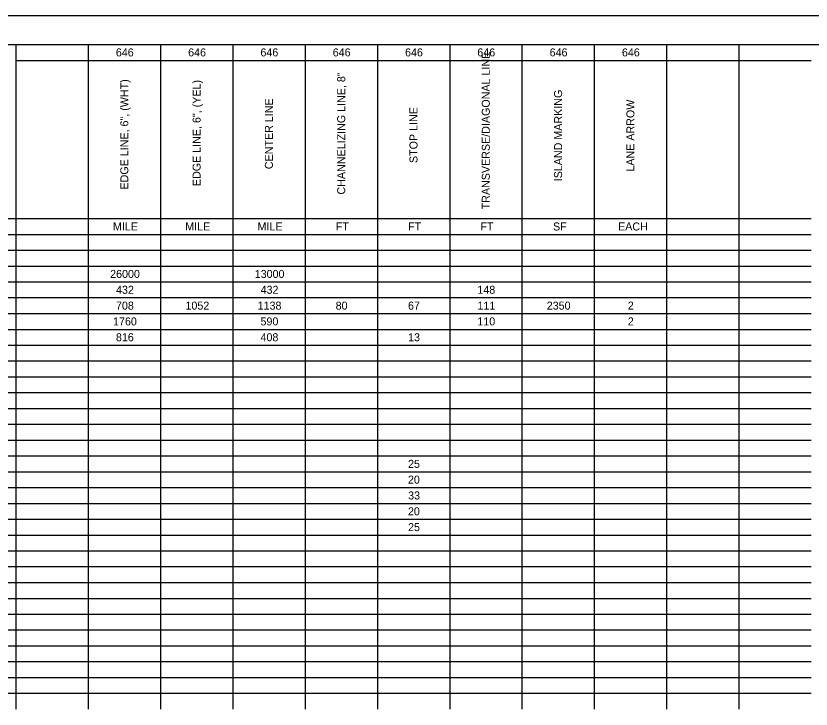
# Model space of a CAD drawing. Extents: x 0 to 34, y 0 to 22.
# Drawn here: x 13.03 to 26.94, y 9.88 to 22 of the extents above; entities that cross this region are included whole.
import ezdxf

# ---------------------------------------------------------------- set-up
doc = ezdxf.new("R2010")
doc.units = 0
for name, color, linetype in [('SH_Border', 7, 'Continuous'), ('SH_Cut_Line', 7, 'Continuous'), ('SH_Text', 7, 'Continuous')]:
    doc.layers.add(name, color=color, linetype=linetype)

msp = doc.modelspace()

# ---------------------------------------------------------------- linework, layer by layer
at = {"layer": 'SH_Border'}
msp.add_lwpolyline([(1.5, 21.5), (33.5, 21.5), (33.5, 0.5), (1.5, 0.5)], close=True, dxfattribs=at)
at = {"layer": 'SH_Cut_Line'}
msp.add_lwpolyline([(0, 0), (34, 0), (34, 22), (0, 22)], close=True, dxfattribs=at)
at = {"layer": 'SH_Text'}
for p, q in [((8.427, 21.5), (13.026, 21.5)), ((13.026, 21.5), (15.556, 21.5)), ((13.026, 21.5), (13.026, 21.223)), ((14.291, 21.5), (14.291, 21.223)), ((15.556, 21.5), (23.145, 21.5)), ((15.556, 21.5), (15.556, 21.223)), ((16.821, 21.5), (16.821, 21.223)), ((18.086, 21.5), (18.086, 21.223)), ((19.351, 21.5), (19.351, 21.223)), ((20.616, 21.5), (20.616, 21.223)), ((21.88, 21.5), (21.88, 21.223)), ((23.145, 21.5), (24.41, 21.5)), ((23.145, 21.5), (23.145, 21.223)), ((24.41, 21.5), (25.675, 21.5)), ((24.41, 21.5), (24.41, 21.223)), ((25.675, 21.5), (26.94, 21.5)), ((25.675, 21.5), (25.675, 21.223)), ((13.026, 21.223), (15.556, 21.223)), ((13.026, 21.223), (13.026, 20.947)), ((14.291, 21.223), (14.291, 20.947)), ((15.556, 21.223), (23.145, 21.223)), ((15.556, 21.223), (15.556, 20.947)), ((16.821, 21.223), (16.821, 20.947)), ((18.086, 21.223), (18.086, 20.947)), ((19.351, 21.223), (19.351, 20.947)), ((20.616, 21.223), (20.616, 20.947)), ((21.88, 21.223), (21.88, 20.947)), ((23.145, 21.223), (24.41, 21.223)), ((23.145, 21.223), (23.145, 20.947)), ((24.41, 21.223), (25.675, 21.223)), ((24.41, 21.223), (24.41, 20.947)), ((25.675, 21.223), (26.94, 21.223)), ((25.675, 21.223), (25.675, 20.947)), ((13.026, 20.947), (13.026, 20.67)), ((14.291, 20.947), (14.291, 20.67)), ((15.556, 20.947), (15.556, 20.67)), ((16.821, 20.947), (16.821, 20.67)), ((18.086, 20.947), (18.086, 20.67)), ((19.351, 20.947), (19.351, 20.67)), ((20.616, 20.947), (20.616, 20.67)), ((21.88, 20.947), (21.88, 20.67)), ((23.145, 20.947), (23.145, 20.67)), ((24.41, 20.947), (24.41, 20.67)), ((25.675, 20.947), (25.675, 20.67)), ((13.026, 20.67), (13.026, 20.393)), ((14.291, 20.67), (14.291, 20.393)), ((15.556, 20.67), (15.556, 20.393)), ((16.821, 20.67), (16.821, 20.393)), ((18.086, 20.67), (18.086, 20.393)), ((19.351, 20.67), (19.351, 20.393)), ((20.616, 20.67), (20.616, 20.393)), ((21.88, 20.67), (21.88, 20.393)), ((23.145, 20.67), (23.145, 20.393)), ((24.41, 20.67), (24.41, 20.393)), ((25.675, 20.67), (25.675, 20.393)), ((13.026, 20.393), (13.026, 20.116)), ((14.291, 20.393), (14.291, 20.116)), ((15.556, 20.393), (15.556, 20.116)), ((16.821, 20.393), (16.821, 20.116)), ((18.086, 20.393), (18.086, 20.116)), ((19.351, 20.393), (19.351, 20.116)), ((20.616, 20.393), (20.616, 20.116)), ((21.88, 20.393), (21.88, 20.116)), ((23.145, 20.393), (23.145, 20.116)), ((24.41, 20.393), (24.41, 20.116)), ((25.675, 20.393), (25.675, 20.116)), ((13.026, 20.116), (13.026, 19.84)), ((14.291, 20.116), (14.291, 19.84)), ((15.556, 20.116), (15.556, 19.84)), ((16.821, 20.116), (16.821, 19.84)), ((18.086, 20.116), (18.086, 19.84)), ((19.351, 20.116), (19.351, 19.84)), ((20.616, 20.116), (20.616, 19.84)), ((21.88, 20.116), (21.88, 19.84)), ((23.145, 20.116), (23.145, 19.84)), ((24.41, 20.116), (24.41, 19.84)), ((25.675, 20.116), (25.675, 19.84)), ((13.026, 19.84), (13.026, 19.563)), ((14.291, 19.84), (14.291, 19.563)), ((15.556, 19.84), (15.556, 19.563)), ((16.821, 19.84), (16.821, 19.563)), ((18.086, 19.84), (18.086, 19.563)), ((19.351, 19.84), (19.351, 19.563)), ((20.616, 19.84), (20.616, 19.563)), ((21.88, 19.84), (21.88, 19.563)), ((23.145, 19.84), (23.145, 19.563)), ((24.41, 19.84), (24.41, 19.563)), ((25.675, 19.84), (25.675, 19.563)), ((13.026, 19.563), (13.026, 19.01)), ((14.291, 19.563), (14.291, 19.01)), ((15.556, 19.563), (15.556, 19.01)), ((16.821, 19.563), (16.821, 19.01)), ((18.086, 19.563), (18.086, 19.01)), ((19.351, 19.563), (19.351, 19.01)), ((20.616, 19.563), (20.616, 19.01)), ((21.88, 19.563), (21.88, 19.01)), ((23.145, 19.563), (23.145, 19.01)), ((24.41, 19.563), (24.41, 19.01)), ((25.675, 19.563), (25.675, 19.01)), ((13.026, 19.01), (13.026, 18.18)), ((14.291, 19.01), (14.291, 18.18)), ((15.556, 19.01), (15.556, 18.18)), ((16.821, 19.01), (16.821, 18.18)), ((18.086, 19.01), (18.086, 18.18)), ((19.351, 19.01), (19.351, 18.18)), ((20.616, 19.01), (20.616, 18.18)), ((21.88, 19.01), (21.88, 18.18)), ((23.145, 19.01), (23.145, 18.18)), ((24.41, 19.01), (24.41, 18.18)), ((25.675, 19.01), (25.675, 18.18)), ((11.761, 18.456), (13.026, 18.456)), ((13.026, 18.456), (15.556, 18.456)), ((15.556, 18.456), (23.145, 18.456)), ((23.145, 18.456), (24.41, 18.456)), ((24.41, 18.456), (25.675, 18.456)), ((25.675, 18.456), (26.94, 18.456)), ((8.427, 18.18), (13.026, 18.18)), ((13.026, 18.18), (15.556, 18.18)), ((13.026, 18.18), (13.026, 17.349)), ((14.291, 18.18), (14.291, 17.349)), ((15.556, 18.18), (23.145, 18.18)), ((15.556, 18.18), (15.556, 17.349)), ((16.821, 18.18), (16.821, 17.349)), ((18.086, 18.18), (18.086, 17.349)), ((19.351, 18.18), (19.351, 17.349)), ((20.616, 18.18), (20.616, 17.349)), ((21.88, 18.18), (21.88, 17.349)), ((23.145, 18.18), (24.41, 18.18)), ((23.145, 18.18), (23.145, 17.349)), ((24.41, 18.18), (25.675, 18.18)), ((24.41, 18.18), (24.41, 17.349)), ((25.675, 18.18), (26.94, 18.18)), ((25.675, 18.18), (25.675, 17.349)), ((8.427, 17.903), (13.026, 17.903)), ((13.026, 17.903), (15.556, 17.903)), ((15.556, 17.903), (23.145, 17.903)), ((23.145, 17.903), (24.41, 17.903)), ((24.41, 17.903), (25.675, 17.903)), ((25.675, 17.903), (26.94, 17.903)), ((8.427, 17.626), (13.026, 17.626)), ((13.026, 17.626), (15.556, 17.626)), ((15.556, 17.626), (23.145, 17.626)), ((23.145, 17.626), (24.41, 17.626)), ((24.41, 17.626), (25.675, 17.626)), ((25.675, 17.626), (26.94, 17.626)), ((8.427, 17.349), (13.026, 17.349)), ((13.026, 17.349), (15.556, 17.349)), ((13.026, 17.349), (13.026, 17.073)), ((14.291, 17.349), (14.291, 17.073)), ((15.556, 17.349), (23.145, 17.349)), ((15.556, 17.349), (15.556, 17.073)), ((16.821, 17.349), (16.821, 17.073)), ((18.086, 17.349), (18.086, 17.073)), ((19.351, 17.349), (19.351, 17.073)), ((20.616, 17.349), (20.616, 17.073)), ((21.88, 17.349), (21.88, 17.073)), ((23.145, 17.349), (24.41, 17.349)), ((23.145, 17.349), (23.145, 17.073)), ((24.41, 17.349), (25.675, 17.349)), ((24.41, 17.349), (24.41, 17.073)), ((25.675, 17.349), (26.94, 17.349)), ((25.675, 17.349), (25.675, 17.073)), ((8.427, 17.073), (13.026, 17.073)), ((13.026, 17.073), (15.556, 17.073)), ((13.026, 17.073), (13.026, 15.966)), ((14.291, 17.073), (14.291, 15.966)), ((15.556, 17.073), (23.145, 17.073)), ((15.556, 17.073), (15.556, 15.966)), ((16.821, 17.073), (16.821, 15.966)), ((18.086, 17.073), (18.086, 15.966)), ((19.351, 17.073), (19.351, 15.966)), ((20.616, 17.073), (20.616, 15.966)), ((21.88, 17.073), (21.88, 15.966)), ((23.145, 17.073), (24.41, 17.073)), ((23.145, 17.073), (23.145, 15.966)), ((24.41, 17.073), (25.675, 17.073)), ((24.41, 17.073), (24.41, 15.966)), ((25.675, 17.073), (26.94, 17.073)), ((25.675, 17.073), (25.675, 15.966)), ((8.427, 16.796), (13.026, 16.796)), ((13.026, 16.796), (15.556, 16.796)), ((15.556, 16.796), (23.145, 16.796)), ((23.145, 16.796), (24.41, 16.796)), ((24.41, 16.796), (25.675, 16.796)), ((25.675, 16.796), (26.94, 16.796)), ((8.427, 16.519), (13.026, 16.519)), ((13.026, 16.519), (15.556, 16.519)), ((15.556, 16.519), (23.145, 16.519)), ((23.145, 16.519), (24.41, 16.519)), ((24.41, 16.519), (25.675, 16.519)), ((25.675, 16.519), (26.94, 16.519)), ((8.427, 16.243), (13.026, 16.243)), ((13.026, 16.243), (15.556, 16.243)), ((15.556, 16.243), (23.145, 16.243)), ((23.145, 16.243), (24.41, 16.243)), ((24.41, 16.243), (25.675, 16.243)), ((25.675, 16.243), (26.94, 16.243)), ((8.427, 15.966), (13.026, 15.966)), ((13.026, 15.966), (15.556, 15.966)), ((13.026, 15.966), (13.026, 15.689)), ((14.291, 15.966), (14.291, 15.689)), ((15.556, 15.966), (23.145, 15.966)), ((15.556, 15.966), (15.556, 15.689)), ((16.821, 15.966), (16.821, 15.689)), ((18.086, 15.966), (18.086, 15.689)), ((19.351, 15.966), (19.351, 15.689)), ((20.616, 15.966), (20.616, 15.689)), ((21.88, 15.966), (21.88, 15.689)), ((23.145, 15.966), (24.41, 15.966)), ((23.145, 15.966), (23.145, 15.689)), ((24.41, 15.966), (25.675, 15.966)), ((24.41, 15.966), (24.41, 15.689)), ((25.675, 15.966), (26.94, 15.966)), ((25.675, 15.966), (25.675, 15.689)), ((8.427, 15.689), (13.026, 15.689)), ((13.026, 15.689), (15.556, 15.689)), ((13.026, 15.689), (13.026, 15.136)), ((14.291, 15.689), (14.291, 15.136)), ((15.556, 15.689), (23.145, 15.689)), ((15.556, 15.689), (15.556, 15.136)), ((16.821, 15.689), (16.821, 15.136)), ((18.086, 15.689), (18.086, 15.136)), ((19.351, 15.689), (19.351, 15.136)), ((20.616, 15.689), (20.616, 15.136)), ((21.88, 15.689), (21.88, 15.136)), ((23.145, 15.689), (24.41, 15.689)), ((23.145, 15.689), (23.145, 15.136)), ((24.41, 15.689), (25.675, 15.689)), ((24.41, 15.689), (24.41, 15.136)), ((25.675, 15.689), (26.94, 15.689)), ((25.675, 15.689), (25.675, 15.136)), ((8.427, 15.412), (13.026, 15.412)), ((13.026, 15.412), (15.556, 15.412)), ((15.556, 15.412), (23.145, 15.412)), ((23.145, 15.412), (24.41, 15.412)), ((24.41, 15.412), (25.675, 15.412)), ((25.675, 15.412), (26.94, 15.412)), ((8.427, 15.136), (13.026, 15.136)), ((13.026, 15.136), (15.556, 15.136)), ((13.026, 15.136), (13.026, 14.582)), ((14.291, 15.136), (14.291, 14.582)), ((15.556, 15.136), (23.145, 15.136)), ((15.556, 15.136), (15.556, 14.582)), ((16.821, 15.136), (16.821, 14.582)), ((18.086, 15.136), (18.086, 14.582)), ((19.351, 15.136), (19.351, 14.582)), ((20.616, 15.136), (20.616, 14.582)), ((21.88, 15.136), (21.88, 14.582)), ((23.145, 15.136), (24.41, 15.136)), ((23.145, 15.136), (23.145, 14.582)), ((24.41, 15.136), (25.675, 15.136)), ((24.41, 15.136), (24.41, 14.582)), ((25.675, 15.136), (26.94, 15.136)), ((25.675, 15.136), (25.675, 14.582)), ((8.427, 14.859), (13.026, 14.859)), ((13.026, 14.859), (15.556, 14.859)), ((15.556, 14.859), (23.145, 14.859)), ((23.145, 14.859), (24.41, 14.859)), ((24.41, 14.859), (25.675, 14.859)), ((25.675, 14.859), (26.94, 14.859)), ((8.427, 14.582), (13.026, 14.582)), ((13.026, 14.582), (15.556, 14.582)), ((13.026, 14.582), (13.026, 14.306)), ((14.291, 14.582), (14.291, 14.306)), ((15.556, 14.582), (23.145, 14.582)), ((15.556, 14.582), (15.556, 14.306)), ((16.821, 14.582), (16.821, 14.306)), ((18.086, 14.582), (18.086, 14.306)), ((19.351, 14.582), (19.351, 14.306)), ((20.616, 14.582), (20.616, 14.306)), ((21.88, 14.582), (21.88, 14.306)), ((23.145, 14.582), (24.41, 14.582)), ((23.145, 14.582), (23.145, 14.306)), ((24.41, 14.582), (25.675, 14.582)), ((24.41, 14.582), (24.41, 14.306)), ((25.675, 14.582), (26.94, 14.582)), ((25.675, 14.582), (25.675, 14.306)), ((8.427, 14.306), (13.026, 14.306)), ((13.026, 14.306), (15.556, 14.306)), ((13.026, 14.306), (13.026, 13.752)), ((14.291, 14.306), (14.291, 13.752)), ((15.556, 14.306), (23.145, 14.306)), ((15.556, 14.306), (15.556, 13.752)), ((16.821, 14.306), (16.821, 13.752)), ((18.086, 14.306), (18.086, 13.752)), ((19.351, 14.306), (19.351, 13.752)), ((20.616, 14.306), (20.616, 13.752)), ((21.88, 14.306), (21.88, 13.752)), ((23.145, 14.306), (24.41, 14.306)), ((23.145, 14.306), (23.145, 13.752)), ((24.41, 14.306), (25.675, 14.306)), ((24.41, 14.306), (24.41, 13.752)), ((25.675, 14.306), (26.94, 14.306)), ((25.675, 14.306), (25.675, 13.752)), ((8.427, 14.029), (13.026, 14.029)), ((13.026, 14.029), (15.556, 14.029)), ((15.556, 14.029), (23.145, 14.029)), ((23.145, 14.029), (24.41, 14.029)), ((24.41, 14.029), (25.675, 14.029)), ((25.675, 14.029), (26.94, 14.029)), ((8.427, 13.752), (13.026, 13.752)), ((13.026, 13.752), (15.556, 13.752)), ((13.026, 13.752), (13.026, 13.476)), ((14.291, 13.752), (14.291, 13.476)), ((15.556, 13.752), (23.145, 13.752)), ((15.556, 13.752), (15.556, 13.476)), ((16.821, 13.752), (16.821, 13.476)), ((18.086, 13.752), (18.086, 13.476)), ((19.351, 13.752), (19.351, 13.476)), ((20.616, 13.752), (20.616, 13.476)), ((21.88, 13.752), (21.88, 13.476)), ((23.145, 13.752), (24.41, 13.752)), ((23.145, 13.752), (23.145, 13.476)), ((24.41, 13.752), (25.675, 13.752)), ((24.41, 13.752), (24.41, 13.476)), ((25.675, 13.752), (26.94, 13.752)), ((25.675, 13.752), (25.675, 13.476)), ((8.427, 13.476), (13.026, 13.476)), ((13.026, 13.476), (15.556, 13.476)), ((13.026, 13.476), (13.026, 12.645)), ((14.291, 13.476), (14.291, 12.645)), ((15.556, 13.476), (23.145, 13.476)), ((15.556, 13.476), (15.556, 12.645)), ((16.821, 13.476), (16.821, 12.645)), ((18.086, 13.476), (18.086, 12.645)), ((19.351, 13.476), (19.351, 12.645)), ((20.616, 13.476), (20.616, 12.645)), ((21.88, 13.476), (21.88, 12.645)), ((23.145, 13.476), (24.41, 13.476)), ((23.145, 13.476), (23.145, 12.645)), ((24.41, 13.476), (25.675, 13.476)), ((24.41, 13.476), (24.41, 12.645)), ((25.675, 13.476), (26.94, 13.476)), ((25.675, 13.476), (25.675, 12.645)), ((8.427, 13.199), (13.026, 13.199)), ((13.026, 13.199), (15.556, 13.199)), ((15.556, 13.199), (23.145, 13.199)), ((23.145, 13.199), (24.41, 13.199)), ((24.41, 13.199), (25.675, 13.199)), ((25.675, 13.199), (26.94, 13.199)), ((8.427, 12.922), (13.026, 12.922)), ((13.026, 12.922), (15.556, 12.922)), ((15.556, 12.922), (23.145, 12.922)), ((23.145, 12.922), (24.41, 12.922)), ((24.41, 12.922), (25.675, 12.922)), ((25.675, 12.922), (26.94, 12.922)), ((8.427, 12.645), (13.026, 12.645)), ((13.026, 12.645), (15.556, 12.645)), ((13.026, 12.645), (13.026, 12.369)), ((14.291, 12.645), (14.291, 12.369)), ((15.556, 12.645), (23.145, 12.645)), ((15.556, 12.645), (15.556, 12.369)), ((16.821, 12.645), (16.821, 12.369)), ((18.086, 12.645), (18.086, 12.369)), ((19.351, 12.645), (19.351, 12.369)), ((20.616, 12.645), (20.616, 12.369)), ((21.88, 12.645), (21.88, 12.369)), ((23.145, 12.645), (24.41, 12.645)), ((23.145, 12.645), (23.145, 12.369)), ((24.41, 12.645), (25.675, 12.645)), ((24.41, 12.645), (24.41, 12.369)), ((25.675, 12.645), (26.94, 12.645)), ((25.675, 12.645), (25.675, 12.369)), ((8.427, 12.369), (13.026, 12.369)), ((13.026, 12.369), (15.556, 12.369)), ((13.026, 12.369), (13.026, 12.092)), ((14.291, 12.369), (14.291, 12.092)), ((15.556, 12.369), (23.145, 12.369)), ((15.556, 12.369), (15.556, 12.092)), ((16.821, 12.369), (16.821, 12.092)), ((18.086, 12.369), (18.086, 12.092)), ((19.351, 12.369), (19.351, 12.092)), ((20.616, 12.369), (20.616, 12.092)), ((21.88, 12.369), (21.88, 12.092)), ((23.145, 12.369), (24.41, 12.369)), ((23.145, 12.369), (23.145, 12.092)), ((24.41, 12.369), (25.675, 12.369)), ((24.41, 12.369), (24.41, 12.092)), ((25.675, 12.369), (26.94, 12.369)), ((25.675, 12.369), (25.675, 12.092)), ((8.427, 12.092), (13.026, 12.092)), ((13.026, 12.092), (15.556, 12.092)), ((13.026, 12.092), (13.026, 11.262)), ((14.291, 12.092), (14.291, 11.262)), ((15.556, 12.092), (23.145, 12.092)), ((15.556, 12.092), (15.556, 11.262)), ((16.821, 12.092), (16.821, 11.262)), ((18.086, 12.092), (18.086, 11.262)), ((19.351, 12.092), (19.351, 11.262)), ((20.616, 12.092), (20.616, 11.262)), ((21.88, 12.092), (21.88, 11.262)), ((23.145, 12.092), (24.41, 12.092)), ((23.145, 12.092), (23.145, 11.262)), ((24.41, 12.092), (25.675, 12.092)), ((24.41, 12.092), (24.41, 11.262)), ((25.675, 12.092), (26.94, 12.092)), ((25.675, 12.092), (25.675, 11.262)), ((8.427, 11.815), (13.026, 11.815)), ((13.026, 11.815), (15.556, 11.815)), ((15.556, 11.815), (23.145, 11.815)), ((23.145, 11.815), (24.41, 11.815)), ((24.41, 11.815), (25.675, 11.815)), ((25.675, 11.815), (26.94, 11.815)), ((8.427, 11.539), (13.026, 11.539)), ((13.026, 11.539), (15.556, 11.539)), ((15.556, 11.539), (23.145, 11.539)), ((23.145, 11.539), (24.41, 11.539)), ((24.41, 11.539), (25.675, 11.539)), ((25.675, 11.539), (26.94, 11.539)), ((8.427, 11.262), (13.026, 11.262)), ((13.026, 11.262), (15.556, 11.262)), ((13.026, 11.262), (13.026, 10.708)), ((14.291, 11.262), (14.291, 10.708)), ((15.556, 11.262), (23.145, 11.262)), ((15.556, 11.262), (15.556, 10.708)), ((16.821, 11.262), (16.821, 10.708)), ((18.086, 11.262), (18.086, 10.708)), ((19.351, 11.262), (19.351, 10.708)), ((20.616, 11.262), (20.616, 10.708)), ((21.88, 11.262), (21.88, 10.708)), ((23.145, 11.262), (24.41, 11.262)), ((23.145, 11.262), (23.145, 10.708)), ((24.41, 11.262), (25.675, 11.262)), ((24.41, 11.262), (24.41, 10.708)), ((25.675, 11.262), (26.94, 11.262)), ((25.675, 11.262), (25.675, 10.708)), ((8.427, 10.985), (13.026, 10.985)), ((13.026, 10.985), (15.556, 10.985)), ((15.556, 10.985), (23.145, 10.985)), ((23.145, 10.985), (24.41, 10.985)), ((24.41, 10.985), (25.675, 10.985)), ((25.675, 10.985), (26.94, 10.985)), ((8.427, 10.708), (13.026, 10.708)), ((13.026, 10.708), (15.556, 10.708)), ((13.026, 10.708), (13.026, 9.878)), ((14.291, 10.708), (14.291, 9.878)), ((15.556, 10.708), (23.145, 10.708)), ((15.556, 10.708), (15.556, 9.878)), ((16.821, 10.708), (16.821, 9.878)), ((18.086, 10.708), (18.086, 9.878)), ((19.351, 10.708), (19.351, 9.878)), ((20.616, 10.708), (20.616, 9.878)), ((21.88, 10.708), (21.88, 9.878)), ((23.145, 10.708), (24.41, 10.708)), ((23.145, 10.708), (23.145, 9.878)), ((24.41, 10.708), (25.675, 10.708)), ((24.41, 10.708), (24.41, 9.878)), ((25.675, 10.708), (26.94, 10.708)), ((25.675, 10.708), (25.675, 9.878)), ((8.427, 10.432), (13.026, 10.432)), ((13.026, 10.432), (15.556, 10.432)), ((15.556, 10.432), (23.145, 10.432)), ((23.145, 10.432), (24.41, 10.432)), ((24.41, 10.432), (25.675, 10.432)), ((25.675, 10.432), (26.94, 10.432)), ((8.427, 10.155), (13.026, 10.155)), ((13.026, 10.155), (15.556, 10.155)), ((15.556, 10.155), (23.145, 10.155)), ((23.145, 10.155), (24.41, 10.155)), ((24.41, 10.155), (25.675, 10.155)), ((25.675, 10.155), (26.94, 10.155))]:
    msp.add_line(p, q, dxfattribs=at)

# ---------------------------------------------------------------- texts
for s, p in [('646', (14.775, 21.292)), ('646', (16.04, 21.292)), ('646', (17.305, 21.292)), ('646', (18.57, 21.292)), ('646', (19.835, 21.292)), ('646', (21.1, 21.292)), ('646', (22.365, 21.292)), ('646', (23.63, 21.292)), ('MILE', (14.724, 18.248)), ('MILE', (15.989, 18.248)), ('MILE', (17.254, 18.248)), ('FT', (18.624, 18.248)), ('FT', (19.889, 18.248)), ('FT', (21.154, 18.248)), ('SF', (22.424, 18.248)), ('EACH', (23.563, 18.248)), ('26000', (14.675, 17.418)), ('13000', (17.205, 17.418)), ('432', (14.778, 17.141)), ('432', (17.308, 17.141)), ('148', (21.101, 17.141)), ('708', (14.777, 16.864)), ('1052', (15.993, 16.864)), ('1138', (17.256, 16.864)), ('80', (18.621, 16.864)), ('67', (19.887, 16.864)), ('111', (21.103, 16.864)), ('2350', (22.315, 16.864)), ('2', (23.733, 16.864)), ('1760', (14.726, 16.588)), ('590', (17.306, 16.588)), ('110', (21.101, 16.588)), ('2', (23.733, 16.588)), ('816', (14.776, 16.311)), ('408', (17.306, 16.311)), ('13', (19.889, 16.311)), ('25', (19.888, 14.097)), ('20', (19.886, 13.821)), ('33', (19.889, 13.544)), ('20', (19.886, 13.267)), ('25', (19.888, 12.99))]:
    msp.add_text(s, height=0.14, dxfattribs=at).set_placement(p)
for s, p in [('TRANSVERSE/DIAGONAL LINE', (21.318, 18.617)), ('EDGE LINE, 6", (WHT)', (14.993, 18.964)), ('CHANNELIZING LINE, 8"', (18.788, 18.876)), ('EDGE LINE, 6", (YEL)', (16.258, 19.024)), ('ISLAND MARKING', (22.583, 19.108)), ('CENTER LINE', (17.523, 19.32)), ('LANE ARROW', (23.848, 19.277)), ('STOP LINE', (20.053, 19.427))]:
    msp.add_text(s, height=0.14, rotation=90, dxfattribs=at).set_placement(p)

doc.saveas('drawing.dxf')
